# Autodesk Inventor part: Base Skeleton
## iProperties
Created: 2006-02
Part Number: Base Skeleton
Document SubType Name: Modeling
Designer: 40664
Density: 1 g/cm^3
Author: 40664
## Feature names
1. Extrusion1
2. Split1
3. Split2
4. Split3
5. Split4
6. Split5
